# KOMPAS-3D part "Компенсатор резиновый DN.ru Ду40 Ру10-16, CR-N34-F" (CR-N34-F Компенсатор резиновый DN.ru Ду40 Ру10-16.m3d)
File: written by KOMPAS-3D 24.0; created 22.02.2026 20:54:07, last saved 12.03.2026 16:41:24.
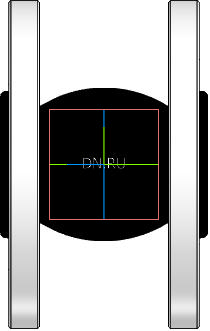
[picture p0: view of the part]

Document properties: Автор: DN.RU; Полное имя файла: CR-N34-F Компенсатор резиновый DN.ru Ду40 Ру10-16.cdw

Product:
- Body: Твердое тело2  | qty 1
    Масса: 4.436857
- Part/product: Компенсатор резиновый DN.ru Ду40 Ру10-16  | designation CR-N34-F
    Масса: 4.5
    Раздел спецификации: Прочие изделия
    Форматы листов документа: A3
    Комментарий: D140-02088
    Примечание: D140-02088
    additional columns: Типовые

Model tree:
1. Твердое тело2  (labels: Твердое тело2)

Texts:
  CR-N34-F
